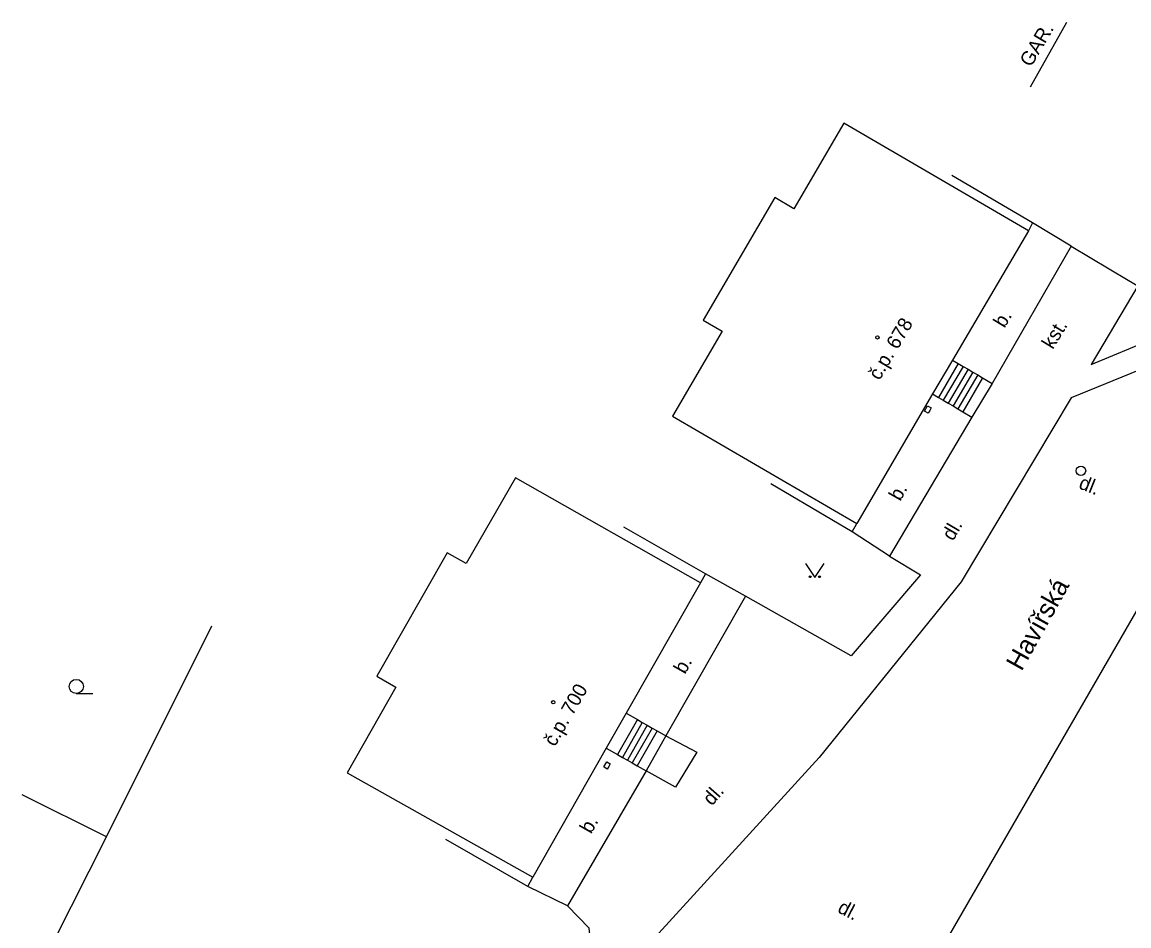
# Model space of a CAD drawing. Extents: x -577457 to -568404, y -1208466 to -1201387.
# Drawn here: x -569068 to -569009.1, y -1203914.6 to -1203866.6 of the extents above; entities that cross this region are included whole.
import ezdxf

# ---------------------------------------------------------------- set-up
doc = ezdxf.new("R2010")
doc.units = 0
for name, color, linetype in [('BUDOVY_MĚŘ', 7, 'Continuous'), ('BUDOVY_NEMĚŘ', 7, 'Continuous'), ('NÁZVY_ULIC_TOK_SMĚR', 7, 'Continuous'), ('OBVOD_PILÍŘE', 7, 'Continuous'), ('POMOC_POPIS', 7, 'Continuous'), ('ROZHRANÍ_PLOCH', 7, 'Continuous'), ('ZN_BUDOV', 7, 'Continuous'), ('ZN_DOPLŇKOVÉ', 7, 'Continuous'), ('ZN_KULTUR', 7, 'Continuous'), ('Č_POPIS_ORIENT', 7, 'Continuous')]:
    doc.layers.add(name, color=color, linetype=linetype)

msp = doc.modelspace()

# ---------------------------------------------------------------- linework, layer by layer
at = {"layer": 'BUDOVY_MĚŘ'}
for points in [[(-569014.47, -1203877.64), (-569018.51, -1203884.51)], [(-569018.51, -1203884.51), (-569019.57, -1203886.31)], [(-569019.57, -1203886.31), (-569023.6, -1203893.19)], [(-569031.91, -1203896.34), (-569035.86, -1203903.27)], [(-569035.86, -1203903.27), (-569036.92, -1203905.13)], [(-569036.92, -1203905.13), (-569040.82, -1203911.98)]]:
    msp.add_lwpolyline(points, dxfattribs=at)
at = {"layer": 'BUDOVY_NEMĚŘ'}
for points in [[(-569014.37, -1203870), (-569012.43, -1203866.56)], [(-569014.47, -1203877.64), (-569024.29, -1203871.92), (-569026.95, -1203876.47), (-569027.95, -1203875.88), (-569031.76, -1203882.4), (-569030.76, -1203882.98), (-569033.4, -1203887.5), (-569023.6, -1203893.19)], [(-569031.91, -1203896.34), (-569041.74, -1203890.76), (-569044.35, -1203895.32), (-569045.36, -1203894.75), (-569049.1, -1203901.31), (-569048.09, -1203901.89), (-569050.68, -1203906.44), (-569040.82, -1203911.98)]]:
    msp.add_lwpolyline(points, dxfattribs=at)
at = {"layer": 'OBVOD_PILÍŘE'}
for points in [[(-569019.72, -1203887.19), (-569019.8, -1203887.33), (-569019.99, -1203887.22), (-569019.83, -1203886.94), (-569019.64, -1203887.05), (-569019.72, -1203887.19)], [(-569036.78, -1203906.1), (-569036.86, -1203906.24), (-569037.05, -1203906.13), (-569036.89, -1203905.85), (-569036.7, -1203905.96), (-569036.78, -1203906.1)]]:
    msp.add_lwpolyline(points, dxfattribs=at)
at = {"layer": 'ROZHRANÍ_PLOCH'}
for points in [[(-569014.25, -1203877.22), (-569018.54, -1203874.7)], [(-569014.25, -1203877.22), (-569014.47, -1203877.64)], [(-569012.2, -1203878.46), (-569014.25, -1203877.22)], [(-569012.2, -1203878.46), (-569016.4, -1203885.75)], [(-569012.2, -1203878.46), (-569009.17, -1203880.26)], [(-569008.65, -1203880.57), (-569011.13, -1203884.74)], [(-569009.17, -1203880.26), (-569008.65, -1203880.57)], [(-569011.13, -1203884.74), (-569001.41, -1203880.71)], [(-569000.47, -1203881.73), (-569012.21, -1203886.52)], [(-569018.2, -1203884.69), (-569019.26, -1203886.5)], [(-569018.51, -1203884.51), (-569018.2, -1203884.69)], [(-569018.2, -1203884.69), (-569017.94, -1203884.85)], [(-569017.94, -1203884.85), (-569019, -1203886.65)], [(-569017.68, -1203885), (-569018.74, -1203886.8)], [(-569017.42, -1203885.15), (-569018.48, -1203886.95)], [(-569017.16, -1203885.3), (-569018.22, -1203887.11)], [(-569017.94, -1203884.85), (-569017.68, -1203885)], [(-569017.68, -1203885), (-569017.42, -1203885.15)], [(-569017.42, -1203885.15), (-569017.16, -1203885.3)], [(-569017.16, -1203885.3), (-569016.91, -1203885.45)], [(-569016.91, -1203885.45), (-569017.96, -1203887.26)], [(-569016.4, -1203885.75), (-569017.48, -1203887.54)], [(-569016.91, -1203885.45), (-569016.4, -1203885.75)], [(-569019.57, -1203886.31), (-569019.26, -1203886.5)], [(-569019.26, -1203886.5), (-569019, -1203886.65)], [(-569012.21, -1203886.52), (-569018.05, -1203896.3)], [(-569019, -1203886.65), (-569018.74, -1203886.8)], [(-569018.74, -1203886.8), (-569018.48, -1203886.95)], [(-569018.48, -1203886.95), (-569018.22, -1203887.11)], [(-569018.22, -1203887.11), (-569017.96, -1203887.26)], [(-569017.48, -1203887.54), (-569021.86, -1203894.93)], [(-569017.96, -1203887.26), (-569017.48, -1203887.54)], [(-569023.85, -1203893.63), (-569028.17, -1203891.09)], [(-569031.63, -1203895.87), (-569035.98, -1203893.39)], [(-569023.85, -1203893.63), (-569023.6, -1203893.19)], [(-569021.86, -1203894.93), (-569023.85, -1203893.63)], [(-569021.86, -1203894.93), (-569020.21, -1203895.93), (-569023.9, -1203900.23), (-569029.52, -1203897.05)], [(-569031.63, -1203895.87), (-569031.91, -1203896.34)], [(-569029.52, -1203897.05), (-569031.63, -1203895.87)], [(-569018.05, -1203896.3), (-569025.6, -1203905.62)], [(-569029.52, -1203897.05), (-569033.75, -1203904.47)], [(-569035.26, -1203903.61), (-569036.31, -1203905.47)], [(-569035.86, -1203903.27), (-569035.26, -1203903.61)], [(-569035.26, -1203903.61), (-569035, -1203903.76)], [(-569035, -1203903.76), (-569036.05, -1203905.62)], [(-569034.73, -1203903.91), (-569035.79, -1203905.76)], [(-569034.47, -1203904.06), (-569035.53, -1203905.91)], [(-569034.21, -1203904.21), (-569035.27, -1203906.06)], [(-569035, -1203903.76), (-569034.73, -1203903.91)], [(-569034.73, -1203903.91), (-569034.47, -1203904.06)], [(-569034.47, -1203904.06), (-569034.21, -1203904.21)], [(-569034.21, -1203904.21), (-569033.75, -1203904.47)], [(-569033.75, -1203904.47), (-569034.8, -1203906.33)], [(-569033.75, -1203904.47), (-569032.1, -1203905.34), (-569033.24, -1203907.21), (-569034.8, -1203906.33)], [(-569036.92, -1203905.13), (-569036.31, -1203905.47)], [(-569025.6, -1203905.62), (-569042.46, -1203924.09)], [(-569036.31, -1203905.47), (-569036.05, -1203905.62)], [(-569036.05, -1203905.62), (-569035.79, -1203905.76)], [(-569035.79, -1203905.76), (-569035.53, -1203905.91)], [(-569035.53, -1203905.91), (-569035.27, -1203906.06)], [(-569034.8, -1203906.33), (-569038.98, -1203913.51)], [(-569035.27, -1203906.06), (-569034.8, -1203906.33)], [(-569041.08, -1203912.47), (-569045.44, -1203909.99)], [(-569041.08, -1203912.47), (-569040.82, -1203911.98)], [(-569038.98, -1203913.51), (-569041.08, -1203912.47)], [(-569043.81, -1203922.61), (-569037.68, -1203915.95), (-569037.82, -1203914.7), (-569038.98, -1203913.51)]]:
    msp.add_lwpolyline(points, dxfattribs=at)
at = {"layer": 'ZN_BUDOV'}
for centre in [(-569022.5, -1203883.31), (-569039.73, -1203902.69)]:
    msp.add_circle(centre, 0.0875, dxfattribs=at)
at = {"layer": 'ZN_DOPLŇKOVÉ'}
for points in [[(-569005.27, -1203891.85), (-569021.31, -1203919.6), (-569007.81, -1203918.52)], [(-569063.48, -1203909.84), (-569057.87, -1203898.63)], [(-569063.48, -1203909.84), (-569067.96, -1203907.61)], [(-569066.26, -1203915.34), (-569063.48, -1203909.84)]]:
    msp.add_lwpolyline(points, dxfattribs=at)
for radius in [0.25, 0.0005]:
    msp.add_circle((-569011.681, -1203890.39), radius, dxfattribs=at)
at = {"layer": 'ZN_KULTUR'}
msp.add_line((-569065.08, -1203902.225), (-569064.205, -1203902.225), dxfattribs=at)
msp.add_lwpolyline([(-569026.33, -1203895.32), (-569025.83, -1203896.07), (-569025.33, -1203895.32)], dxfattribs=at)
for centre, radius in [((-569026.08, -1203896.02), 0.05), ((-569025.58, -1203896.02), 0.05), ((-569065.08, -1203901.85), 0.375)]:
    msp.add_circle(centre, radius, dxfattribs=at)

# ---------------------------------------------------------------- texts
at = {"layer": 'NÁZVY_ULIC_TOK_SMĚR'}
msp.add_text('Havířská', height=1, rotation=60.87, dxfattribs=at).set_placement((-569014.84, -1203901.08))
at = {"layer": 'POMOC_POPIS'}
for s, rotation, p in [('GAR.', 59.33998, (-569014.34, -1203868.99)), ('b.', 58.75997, (-569015.75, -1203882.85)), ('kst.', 58.52002, (-569013.18, -1203883.98)), ('dl.', 338.20003, (-569011.85, -1203891.31)), ('b.', 60.16, (-569021.29, -1203892.05)), ('dl.', 59.61001, (-569018.48, -1203894.16)), ('b.', 60.32999, (-569032.73, -1203901.24)), ('dl.', 48.76003, (-569031.3, -1203908.23)), ('b.', 60.32999, (-569037.72, -1203909.72)), ('dl.', 332.71997, (-569024.67, -1203913.82))]:
    msp.add_text(s, height=0.75, rotation=rotation, dxfattribs=at).set_placement(p)
at = {"layer": 'Č_POPIS_ORIENT'}
for s, rotation, p in [('č.p. 678', 59.57999, (-569022.39, -1203885.63)), ('č.p. 700', 60.32999, (-569039.64, -1203905.09))]:
    msp.add_text(s, height=0.75, rotation=rotation, dxfattribs=at).set_placement(p)

doc.saveas('drawing.dxf')
